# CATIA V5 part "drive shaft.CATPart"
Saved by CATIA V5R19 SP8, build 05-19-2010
Part number: drive shaft
Bounding box of the stored display mesh (mm): x -2 to 2, y 105.1 to 563.1, z -2 to 2
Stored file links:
  G:\EU_thinkMotion\CFAO_2010\MMS_groupe1\MMS_groupe1\A reprendre\gduval\CFAO kinematic ok\drive shaft.CATPart
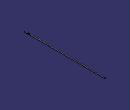
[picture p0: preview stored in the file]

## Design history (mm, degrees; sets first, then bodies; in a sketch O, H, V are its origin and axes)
Body1 (main body)
  Plane1 to Plane3: stored without definition
  Point1: stored without definition
  Line1: type Normal, RefPoint Point1, RefSkin Plane2, Start 0, End 20
  Plane4: stored without definition
  Line2: type Normal, RefPoint Point1, RefSkin Plane4, Start -20, End 20
  Sketch1 on Plane1, origin (0, 543.1, 0), H (-1, 0, 0), V (0, 0, 1)
    circle A1 centre (0, 0) radius 2
    radius A1 = 2
  Pad1: profile Sketch1, direction (0, 1, 0), length 20, opposite side up to Plane3
  Sketch2 on end face of Pad1, origin (0, 563.1, 0), H (-1, 0, 0), V (0, 0, 1)
    point P1 (-1, 1.118)
    line L1 (1, 1.118) -> (1, -1.118)
    line L2 (-1, -1.118) -> (-1, 1.118)
    point P3 (1, -1.118)
    arc A1 centre (0, 0) radius 1.5 from (1, 1.118) to (-1, 1.118) ccw
    point P5 (-1, 1.118)
    arc A2 centre (0, 0) radius 1.5 from (-1, -1.118) to (1, -1.118) ccw
    point P6 (1, -1.118)
    distance L1 V = 1
    distance L2 V = 1
    distance A1 H = 1.5
    distance H A2 = 1.5
    vertical: L1 V, L2 V
    coincidence: P5 L2, P5 P1, P3 P6
  Pocket1: profile Sketch2, direction (0, -1, 0), length 5
  Sketch3 on Plane4, origin (0, 0, 0), H (1, 0, 0), V (0, 1, 0)
    construction line L1 (0, 135.1518) -> (0, 126.676)
    point P1 (0, 135.1518)
    line L2 (0.95, 135.1518) -> (0.95, 126.676)
    line L3 (-0.95, 126.676) -> (-0.95, 135.1518)
    arc A1 centre (0, 126.676) radius 0.95 from (0.95, 126.676) to (-0.95, 126.676) cw
    arc A2 centre (0, 135.1518) radius 0.95 from (-0.95, 135.1518) to (0.95, 135.1518) cw
    distance L3 L2 = 1.9
    coincidence: P1 V
    vertical: L1 V
    tangency: A1 L2, A2 L2, A1 L3, A2 L3
  Pocket2: profile Sketch3, direction (0, 0, 1), through (limit type 6)
  Chamfer1: length 0.5, angle 45, on edge [start face of Pad1 | face of Pad1 from Sketch1.A1]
